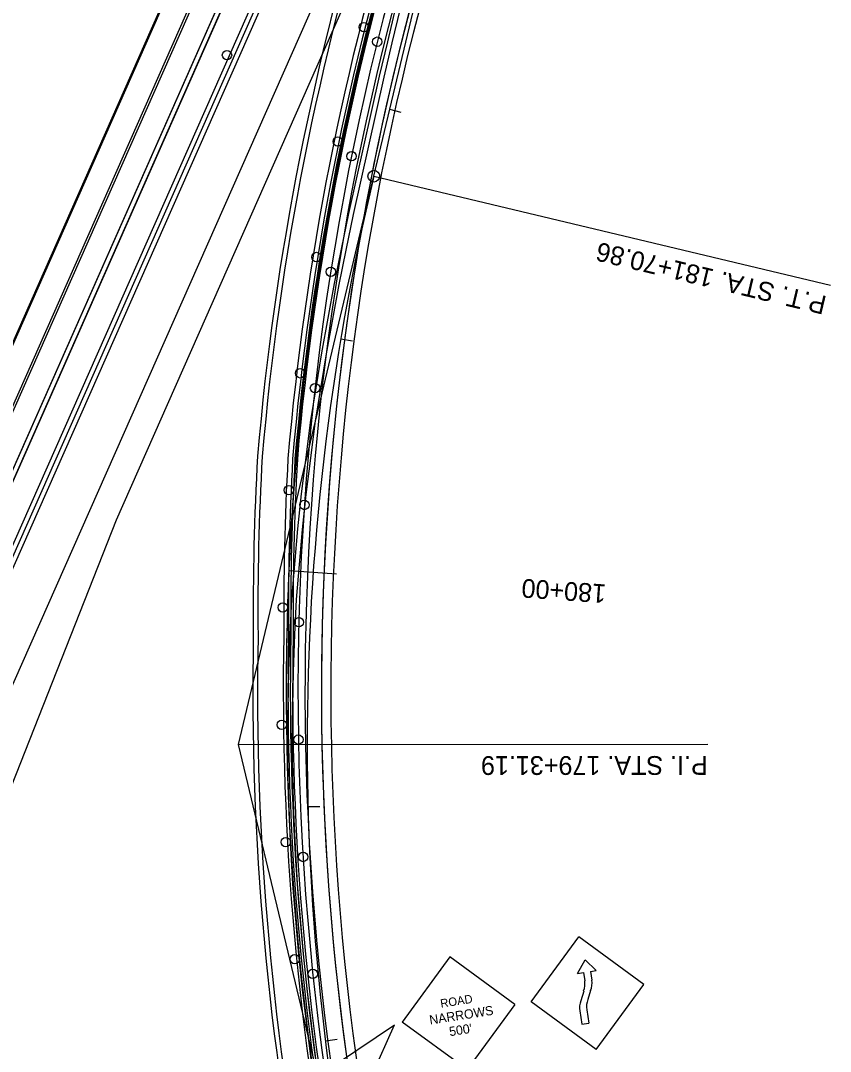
# Model space of a CAD drawing. Extents: x 659657 to 668193, y 633084 to 648639.
# Drawn here: x 662394.7 to 662739.7, y 642694.4 to 643133.4 of the extents above; entities that cross this region are included whole.
import ezdxf

# ---------------------------------------------------------------- set-up
doc = ezdxf.new("R2010")
doc.units = 0
for name, color, linetype in [('R_Draft', 7, 'Continuous'), ('R_MOT_Stage 1A', 7, 'Continuous'), ('R_MOT_Stage 1A_Striping', 7, 'Continuous'), ('R_MOT_Stage 1B', 7, 'Continuous'), ('R_MOT_Stage 1B_Striping', 7, 'Continuous'), ('R_MOT_Stage 1C', 7, 'Continuous'), ('R_MOT_Stage 1C_Striping', 7, 'Continuous'), ('R_MOT_Stage 2', 7, 'Continuous'), ('R_MOT_Stage 2_Striping', 7, 'Continuous'), ('R_MOT_Stage 3', 7, 'Continuous'), ('R_MOT_Stage 3_Striping', 7, 'Continuous'), ('R_MOT_Stage 3_Striping_PPM', 7, 'Continuous'), ('R_MOT_Stage 4_Striping', 7, 'Continuous'), ('R_MOT_Stage 4_Striping_PPM', 7, 'Continuous'), ('R_MOT_Stage 5_Striping_PPM', 7, 'Continuous'), ('T_SIGNAL CONTROL CABINET', 7, 'Continuous')]:
    doc.layers.add(name, color=color, linetype=linetype)

msp = doc.modelspace()

# ---------------------------------------------------------------- linework, layer by layer
at = {"layer": 'R_Draft'}
for p, q in [((662612.23, 642715.43), (662632.49, 642743.19)), ((662660.25, 642722.91), (662632.49, 642743.19)), ((662577.54, 642734.65), (662557.25, 642706.88)), ((662605.31, 642714.36), (662577.54, 642734.65)), ((662632.01, 642727.61), (662635.19, 642733.4)), ((662635.19, 642733.4), (662639.98, 642728.85)), ((662637.49, 642728.46), (662639.98, 642728.85)), ((662632.01, 642727.61), (662634.5, 642728)), ((662634.5, 642728), (662635.05, 642724.46)), ((662637.49, 642728.46), (662638.08, 642724.67)), ((662634.65, 642720.09), (662633.45, 642715.96)), ((662637.57, 642720.33), (662636.44, 642716.43)), ((662639.97, 642695.15), (662660.25, 642722.91)), ((662605.31, 642714.36), (662585.02, 642686.61)), ((662639.97, 642695.15), (662612.23, 642715.43)), ((662632.91, 642711.62), (662633.79, 642706)), ((662635.9, 642712.08), (662636.77, 642706.46)), ((662585.02, 642686.61), (662557.25, 642706.88)), ((662513.25, 642678.4), (662553.98, 642705.66)), ((662543.65, 642682.54), (662553.98, 642705.66)), ((662633.79, 642706), (662636.77, 642706.46))]:
    msp.add_line(p, q, dxfattribs=at)
for centre, start, end in [((662627.65, 642723.13), 336.411, 10.1689), ((662630.68, 642723.34), 336.411, 10.1689), ((662640.32, 642712.94), 156.411, 190.1689), ((662643.34, 642713.41), 156.411, 190.1689)]:
    msp.add_arc(centre, 7.52, start, end, dxfattribs=at)
at = {"layer": 'R_MOT_Stage 1A'}
for points in [[(662518.54, 642691.02), (662516.58, 642705.9), (662514.85, 642720.8), (662513.21, 642735.71), (662511.91, 642750.65), (662510.7, 642765.61), (662509.84, 642781.24), (662509.11, 642796.23), (662508.71, 642811.22), (662508.45, 642826.22), (662508.63, 642841.23), (662508.91, 642856.24), (662509.56, 642871.99), (662510.3, 642886.97), (662511.5, 642901.93), (662512.76, 642916.87), (662514.3, 642931.8), (662516.31, 642947.32), (662518.24, 642962.21), (662520.62, 642977.02), (662523.01, 642991.83), (662525.7, 643006.59), (662528.39, 643021.34), (662531.4, 643036.05), (662534.51, 643051.19), (662537.78, 643065.83), (662541.05, 643080.47), (662544.34, 643095.1), (662547.63, 643109.74), (662551.12, 643124.33), (662554.61, 643138.95)], [(662520.53, 642691.28), (662518.56, 642706.14), (662516.84, 642721.02), (662515.2, 642735.91), (662513.9, 642750.82), (662512.7, 642765.74), (662511.84, 642781.35), (662511.11, 642796.3), (662510.71, 642811.27), (662510.45, 642826.23), (662510.63, 642841.2), (662510.91, 642856.18), (662511.56, 642871.9), (662512.3, 642886.84), (662513.49, 642901.76), (662514.76, 642916.69), (662516.29, 642931.57), (662518.29, 642947.07), (662520.22, 642961.92), (662522.59, 642976.7), (662524.98, 642991.49), (662527.66, 643006.23), (662530.36, 643020.96), (662533.36, 643035.65), (662536.46, 643050.77), (662539.73, 643065.39), (662543.01, 643080.03), (662546.3, 643094.67), (662549.58, 643109.29), (662553.06, 643123.87), (662556.56, 643138.49)]]:
    msp.add_lwpolyline(points, dxfattribs=at)
at = {"layer": 'R_MOT_Stage 1A_Striping'}
for p, q in [((662545.19, 643067.11), (662632.25, 643432.4)), ((662487.49, 642825.07), (662545.19, 643067.11)), ((662545.42, 642583.07), (662487.49, 642825.07))]:
    msp.add_line(p, q, dxfattribs=at)
for points in [[(662520.53, 642691.28), (662518.56, 642706.14), (662516.84, 642721.02), (662515.2, 642735.91), (662513.9, 642750.82), (662512.7, 642765.74), (662511.84, 642781.35), (662511.11, 642796.3), (662510.71, 642811.27), (662510.45, 642826.23), (662510.63, 642841.2), (662510.91, 642856.18), (662511.56, 642871.9), (662512.3, 642886.84), (662513.49, 642901.76), (662514.76, 642916.69), (662516.29, 642931.57), (662518.29, 642947.07), (662520.22, 642961.92), (662522.59, 642976.7), (662524.98, 642991.49), (662527.66, 643006.23), (662530.36, 643020.96), (662533.36, 643035.65), (662536.46, 643050.77), (662539.73, 643065.39), (662543.01, 643080.03), (662546.3, 643094.67), (662549.58, 643109.29), (662553.06, 643123.87), (662556.56, 643138.49)], [(662556.81, 643094.3), (662551.94, 643095.46)], [(662545.19, 643067.11), (662739.74, 643020.74)], [(662536.04, 642996.85), (662531.11, 642997.68)], [(662509.37, 642899.11), (662529.32, 642897.71)], [(662487.49, 642825.07), (662687.49, 642825.16)], [(662522.15, 642798.6), (662517.15, 642798.47)], [(662529.51, 642699.39), (662524.55, 642698.78)]]:
    msp.add_lwpolyline(points, dxfattribs=at)
msp.add_circle((662545.19, 643067.11), 2.5, dxfattribs=at)
msp.add_arc((663558.54, 642825.58), 1041.74, 166.59359, 193.46139, dxfattribs=at)
at = {"layer": 'R_MOT_Stage 1B'}
msp.add_circle((662482.62, 643118.68), 2, dxfattribs=at)
for centre, radius, start, end in [((663661.27, 642847.83), 1169.92, 162.55479, 175.09387), ((663661.27, 642847.83), 1154.92, 162.55478, 175.08437), ((663661.27, 642847.83), 1154.92, 162.55478, 175.08437), ((663661.27, 642847.83), 1152.92, 162.55478, 175.08289), ((663661.27, 642847.83), 1152.92, 162.55478, 175.08289), ((663663.09, 642882.17), 1169.3, 176.77801, 180.52801), ((663663.09, 642882.17), 1154.3, 176.7904, 180.5404), ((663663.09, 642882.17), 1154.3, 176.7904, 180.5404), ((663663.09, 642882.17), 1152.3, 176.79188, 180.54188), ((663663.09, 642882.17), 1152.3, 176.79188, 180.54188), ((663661.27, 642847.83), 1167.67, 178.84387, 191.54523), ((663661.27, 642847.83), 1152.67, 178.83435, 191.54523), ((663661.27, 642847.83), 1152.67, 178.83435, 191.54523), ((663661.27, 642847.83), 1150.67, 178.83287, 191.54523), ((663661.27, 642847.83), 1150.67, 178.83287, 191.54523)]:
    msp.add_arc(centre, radius, start, end, dxfattribs=at)
at = {"layer": 'R_MOT_Stage 1B_Striping'}
for p, q in [((662545.19, 643067.11), (662632.25, 643432.4)), ((662487.49, 642825.07), (662545.19, 643067.11)), ((662545.42, 642583.07), (662487.49, 642825.07))]:
    msp.add_line(p, q, dxfattribs=at)
for points in [[(662556.81, 643094.3), (662551.94, 643095.46)], [(662545.19, 643067.11), (662739.74, 643020.74)], [(662536.04, 642996.85), (662531.11, 642997.68)], [(662509.37, 642899.11), (662529.32, 642897.71)], [(662487.49, 642825.07), (662687.49, 642825.16)], [(662522.15, 642798.6), (662517.15, 642798.47)], [(662529.51, 642699.39), (662524.55, 642698.78)]]:
    msp.add_lwpolyline(points, dxfattribs=at)
msp.add_circle((662545.19, 643067.11), 2.5, dxfattribs=at)
for centre, radius, start, end in [((663661.27, 642847.83), 1167.92, 162.55479, 175.09387), ((663661.27, 642847.83), 1156.92, 162.55479, 175.08585), ((663558.54, 642825.58), 1041.74, 166.59359, 193.46139), ((663663.09, 642882.17), 1167.3, 176.7809, 180.5309), ((663663.09, 642882.17), 1156.3, 176.78892, 180.53892), ((663661.27, 642847.83), 1165.67, 178.84387, 191.54523), ((663661.27, 642847.83), 1154.67, 178.83583, 191.54523)]:
    msp.add_arc(centre, radius, start, end, dxfattribs=at)
at = {"layer": 'R_MOT_Stage 1C'}
for centre in [(662546.66, 643124.39), (662535.68, 643075.62), (662526.83, 643026.41), (662520.13, 642976.87), (662515.6, 642927.08), (662513.23, 642877.14), (662513.04, 642827.14), (662515.03, 642777.18), (662519.19, 642727.36)]:
    msp.add_circle(centre, 2, dxfattribs=at)
at = {"layer": 'R_MOT_Stage 1C_Striping'}
for radius, start in [(1145.42, 158.42034), (1134.42, 158.41207)]:
    msp.add_arc((663661.27, 642847.83), radius, start, 191.54523, dxfattribs=at)
at = {"layer": 'R_MOT_Stage 2'}
msp.add_lwpolyline([(662645.5, 643511.36), (661880.49, 641783.11), (661878.66, 641783.92), (662643.67, 643512.17)], close=True, dxfattribs=at)
for centre in [(662540.99, 643130.57), (662529.8, 643081.84), (662520.74, 643032.68), (662513.81, 642983.16), (662509.03, 642933.39), (662506.41, 642883.47), (662505.95, 642833.47), (662507.65, 642783.51), (662511.51, 642733.66)]:
    msp.add_circle(centre, 2, dxfattribs=at)
at = {"layer": 'R_MOT_Stage 2_Striping'}
for p, q in [((662653.91, 643589.66), (661803.9, 641669.37)), ((661813.96, 641664.92), (662663.97, 643585.2))]:
    msp.add_line(p, q, dxfattribs=at)
msp.add_lwpolyline([(661878.66, 641783.92), (662674.03, 643580.75)], dxfattribs=at)
for radius in [1153.42, 1138.42]:
    msp.add_arc((663661.27, 642847.83), radius, 163.84387, 191.54523, dxfattribs=at)
at = {"layer": 'R_MOT_Stage 3'}
for p, q in [((662227.19, 642534.22), (662595.25, 643365.71)), ((662229.06, 642533.51), (662597.09, 643364.94))]:
    msp.add_line(p, q, dxfattribs=at)
at = {"layer": 'R_MOT_Stage 3_Striping'}
for p, q in [((662215.01, 642538.82), (662583.35, 643370.94)), ((662225.31, 642534.93), (662593.4, 643366.49))]:
    msp.add_line(p, q, dxfattribs=at)
at = {"layer": 'R_MOT_Stage 3_Striping_PPM'}
for p, q in [((661859, 641792.62), (662694.85, 643680.89)), ((661869.52, 641787.96), (662705.36, 643676.24))]:
    msp.add_line(p, q, dxfattribs=at)
for radius, start in [(1153.42, 158.42628), (1138.42, 158.41509)]:
    msp.add_arc((663661.27, 642847.83), radius, start, 191.54523, dxfattribs=at)
at = {"layer": 'R_MOT_Stage 4_Striping'}
for p, q in [((662215.01, 642538.82), (662583.35, 643370.94)), ((662225.31, 642534.93), (662593.4, 643366.49))]:
    msp.add_line(p, q, dxfattribs=at)
at = {"layer": 'R_MOT_Stage 4_Striping_PPM'}
for p, q in [((661859, 641792.62), (662694.85, 643680.89)), ((661869.52, 641787.96), (662705.36, 643676.24))]:
    msp.add_line(p, q, dxfattribs=at)
for radius, start in [(1153.42, 158.42628), (1138.42, 158.41509)]:
    msp.add_arc((663661.27, 642847.83), radius, start, 191.54523, dxfattribs=at)
at = {"layer": 'R_MOT_Stage 5_Striping_PPM'}
for p, q in [((661859, 641792.62), (662694.85, 643680.89)), ((661869.52, 641787.96), (662705.36, 643676.24)), ((662215.01, 642538.82), (662716.34, 643671.38)), ((662125.58, 642250.33), (662543.15, 643193.66)), ((662435.5, 642920.82), (662554.12, 643188.8)), ((662325.04, 642641.64), (662435.5, 642920.82))]:
    msp.add_line(p, q, dxfattribs=at)
for radius, start in [(1153.42, 158.42628), (1138.42, 158.41509)]:
    msp.add_arc((663661.27, 642847.83), radius, start, 191.54523, dxfattribs=at)
at = {"layer": 'T_SIGNAL CONTROL CABINET'}
for centre, radius, start, end in [((663661.27, 642847.83), 1148.42, 156.12343, 191.54523), ((663661.27, 642847.83), 1153.92, 162.59387, 175.08363), ((663663.09, 642882.17), 1153.3, 176.79114, 180.54114), ((663661.27, 642847.83), 1151.67, 178.83361, 191.54523)]:
    msp.add_arc(centre, radius, start, end, dxfattribs=at)

# ---------------------------------------------------------------- texts
at = {"layer": 'R_Draft'}
for s, height, rotation, p in [('ROAD', 3.583, 8.8428, (662573.81, 642712.96)), ('NARROWS', 3.94, 8.8424, (662569.17, 642705.79)), ("500'", 3.94, 8.8424, (662577.61, 642700.83))]:
    msp.add_text(s, height=height, rotation=rotation, dxfattribs=at).set_placement(p)
at = {"layer": 'R_MOT_Stage 1A_Striping'}
for s, rotation, p in [('P.T. STA. 181+70.86', 166.5936, (662738.58, 643015.88)), ('180+00', 175.9911, (662644.37, 642893.19)), ('P.I. STA. 179+31.19', 180.0275, (662687.5, 642820.16))]:
    msp.add_text(s, height=8, rotation=rotation, dxfattribs=at).set_placement(p)
at = {"layer": 'R_MOT_Stage 1B_Striping'}
for s, rotation, p in [('P.T. STA. 181+70.86', 166.5936, (662738.58, 643015.88)), ('180+00', 175.9911, (662644.37, 642893.19)), ('P.I. STA. 179+31.19', 180.0275, (662687.5, 642820.16))]:
    msp.add_text(s, height=8, rotation=rotation, dxfattribs=at).set_placement(p)

doc.saveas('drawing.dxf')
